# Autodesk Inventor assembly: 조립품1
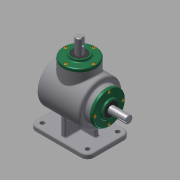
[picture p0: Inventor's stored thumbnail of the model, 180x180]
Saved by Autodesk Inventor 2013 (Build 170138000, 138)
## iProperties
Created: 2016-09
Part Number: 조립품1
Document SubType Name: Assembly
Designer: Administrator
Author: Administrator
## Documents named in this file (14)
- C:\Users\Administrator\Desktop\460908V1014\조립품1.iam
- C:\Users\Administrator\Desktop\460908V1014\본체.ipt
- C:\Users\Administrator\Desktop\460908V1014\M4.ipt
- C:\Users\Administrator\Desktop\460908V1014\메인 베벨기어.ipt
- C:\Users\Administrator\Desktop\460908V1014\메인 축.ipt
- 메인 축.ipt
- C:\Users\Administrator\Desktop\460908V1014\베어링 6203.ipt
- C:\Users\Administrator\Desktop\460908V1014\서브 베벨기어.ipt
- C:\Users\Administrator\Desktop\460908V1014\서브 축.ipt
- 서브 축.ipt
- C:\Users\Administrator\Desktop\460908V1014\오일실 17 32 8.ipt
- C:\Users\Administrator\Desktop\460908V1014\커버.ipt
- C:\Users\Administrator\Desktop\460908V1014\키 4x4.ipt
- C:\Users\Administrator\Desktop\460908V1014\키 5x5.ipt
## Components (8 placed, 1 different names)
1. M4:1 — 각도:1
2. M4:3
3. M4:4
4. M4:5
5. M4:2 — 각도:2
6. M4:6
7. M4:7
8. M4:8
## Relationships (2: Angle 2)
- 각도:1 [Angle]: M4:1
- 각도:2 [Angle]: M4:2
